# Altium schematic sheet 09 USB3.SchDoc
size 420 x 297 mm
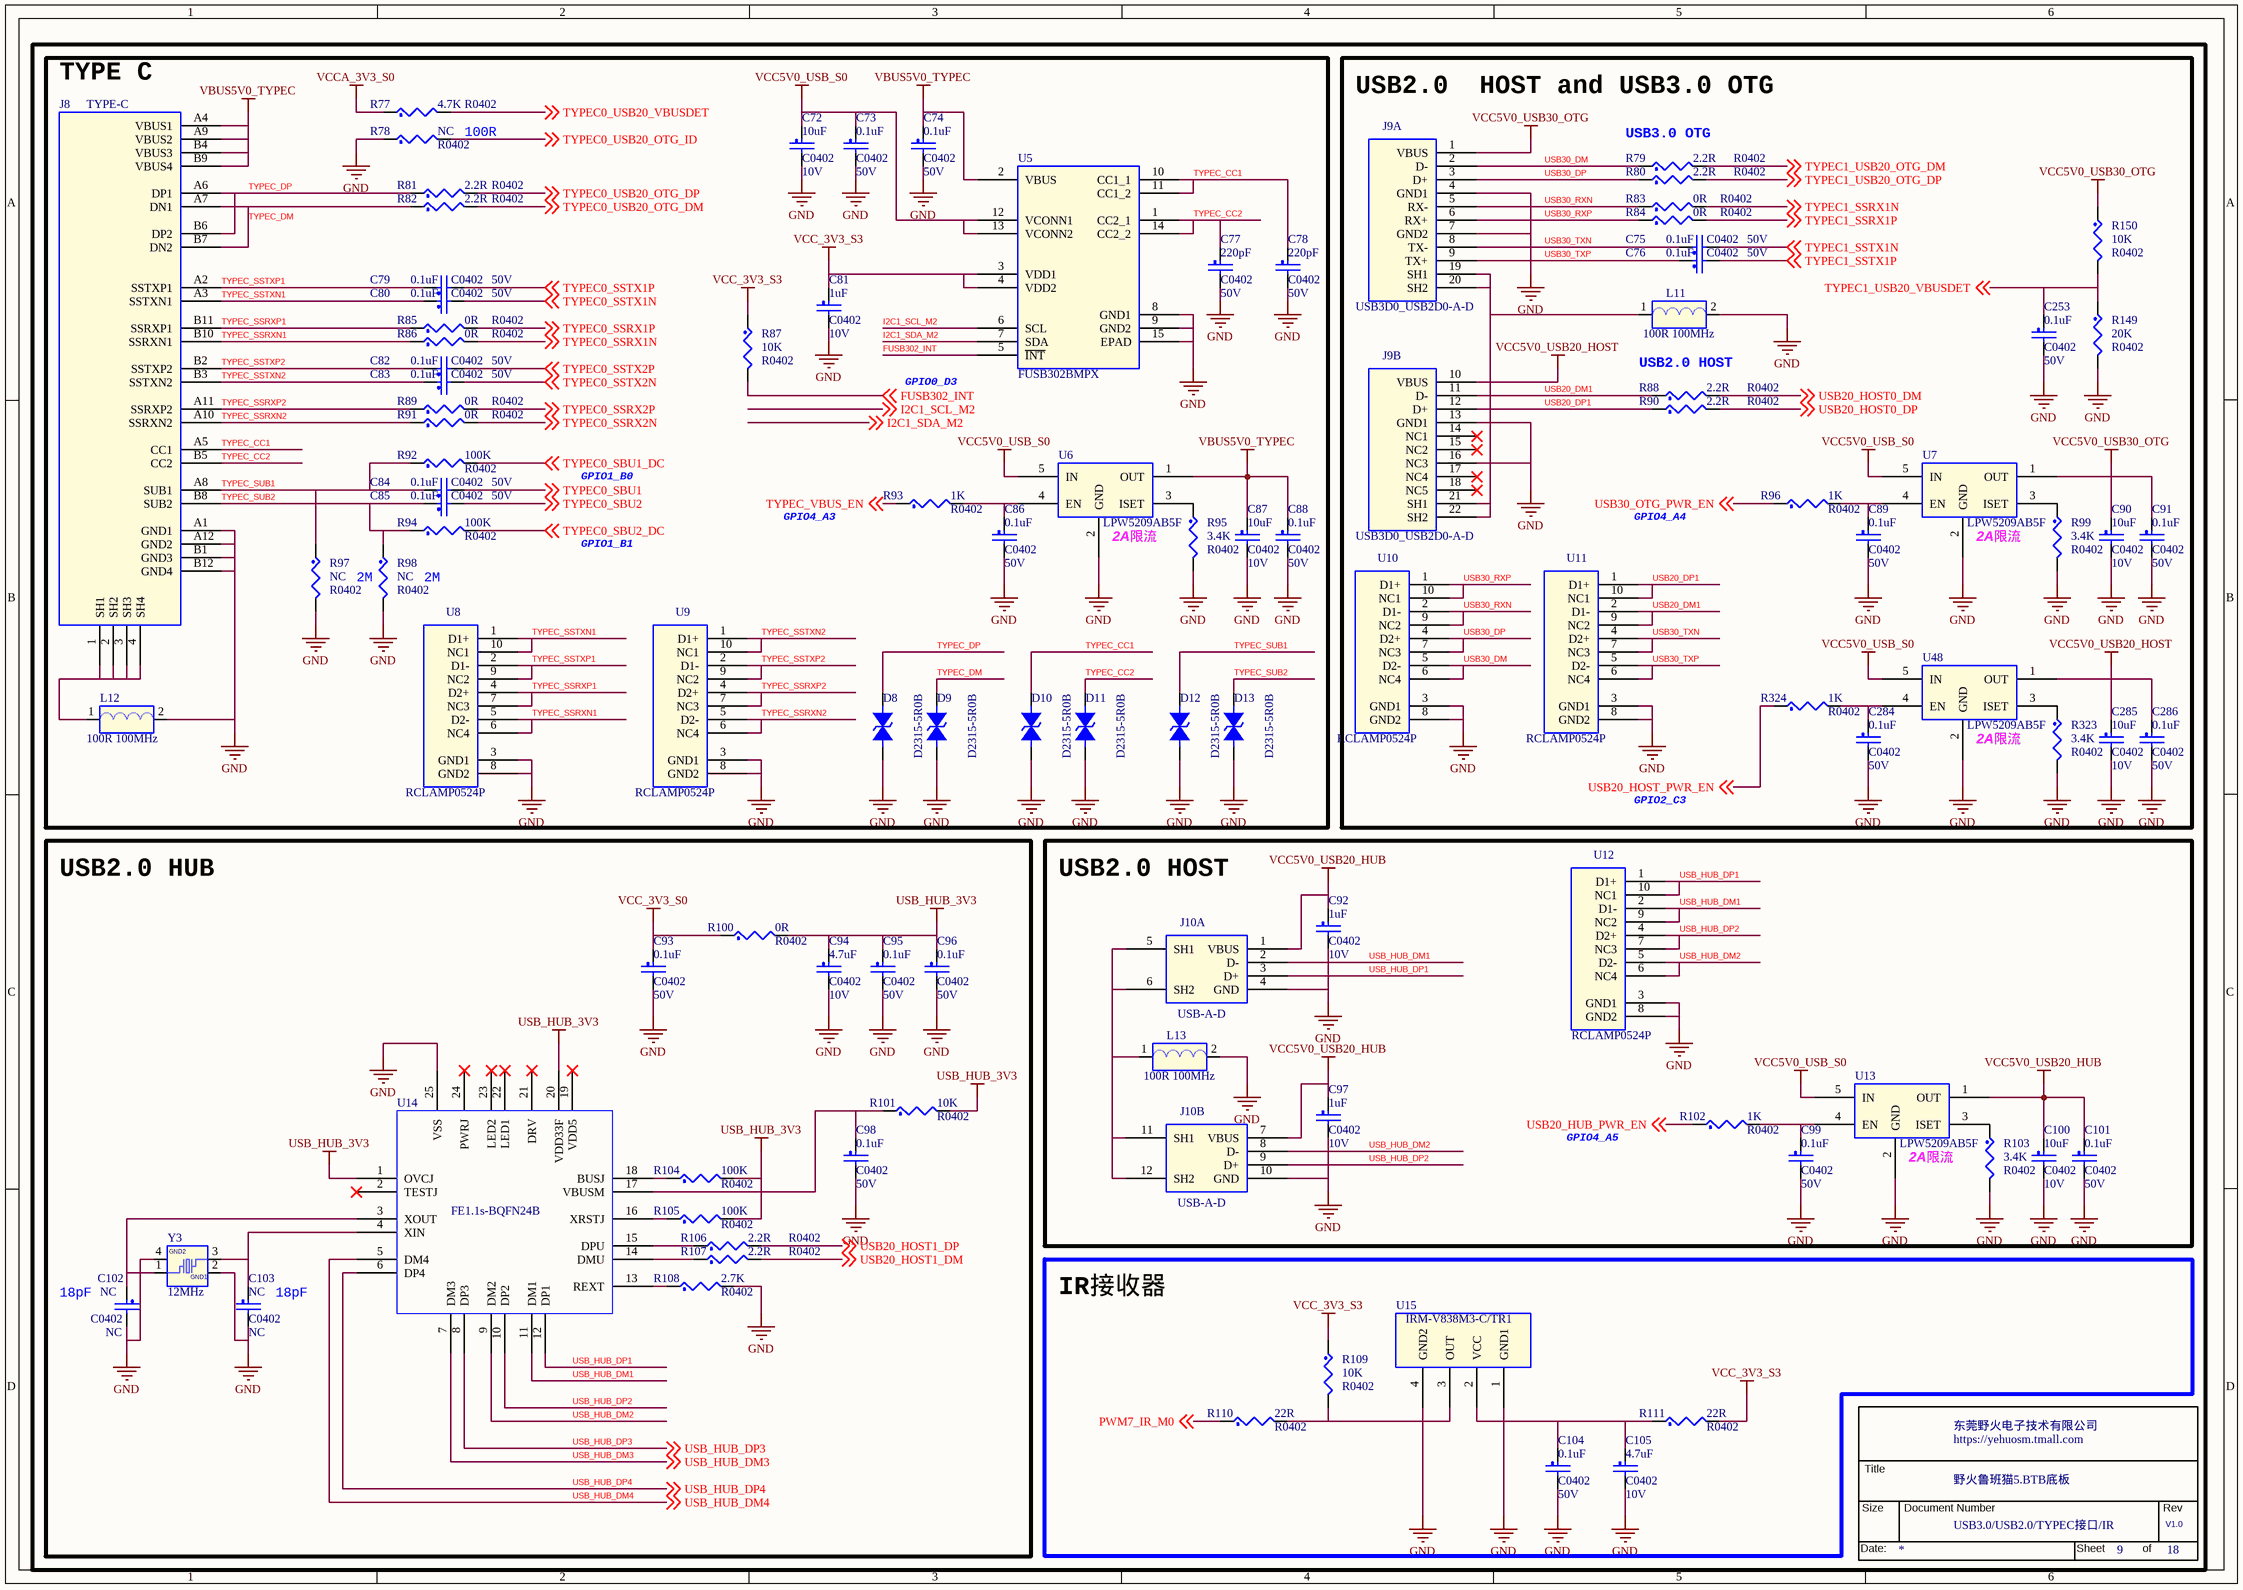
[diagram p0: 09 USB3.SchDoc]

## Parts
*  Doc: USB3.0/USB2.0/TYPEC接口/IR  RevCode: V1.0  Title: 野火鲁班猫5.BTB底板  OrgName: 东莞野火电子技术有限公司  Page Number: 9  Page Count: 18  (hidden comment: TitleBlock_YHSCH)  (graphical)
C72  10uF  Voltage: 10V  [C0402]
C73  0.1uF  Voltage: 50V  [C0402]
C74  0.1uF  Voltage: 50V  [C0402]
C75  0.1uF  Voltage: 50V  [C0402]
C76  0.1uF  Voltage: 50V  [C0402]
C77  220pF  Voltage: 50V  [C0402]
C78  220pF  Voltage: 50V  [C0402]
C79  0.1uF  Voltage: 50V  [C0402]
C80  0.1uF  Voltage: 50V  [C0402]
C81  1uF  Voltage: 10V  [C0402]
C82  0.1uF  Voltage: 50V  [C0402]
C83  0.1uF  Voltage: 50V  [C0402]
C84  0.1uF  Voltage: 50V  [C0402]
C85  0.1uF  Voltage: 50V  [C0402]
C86  0.1uF  Voltage: 50V  [C0402]
C87  10uF  Voltage: 10V  [C0402]
C88  0.1uF  Voltage: 50V  [C0402]
C89  0.1uF  Voltage: 50V  [C0402]
C90  10uF  Voltage: 10V  [C0402]
C91  0.1uF  Voltage: 50V  [C0402]
C92  1uF  Voltage: 10V  [C0402]
C93  0.1uF  Voltage: 50V  [C0402]
C94  4.7uF  Voltage: 10V  [C0402]
C95  0.1uF  Voltage: 50V  [C0402]
C96  0.1uF  Voltage: 50V  [C0402]
C97  1uF  Voltage: 10V  [C0402]
C98  0.1uF  Voltage: 50V  [C0402]
C99  0.1uF  Voltage: 50V  [C0402]
C100  10uF  Voltage: 10V  [C0402]
C101  0.1uF  Voltage: 50V  [C0402]
C102  NC  [C0402]
C103  NC  [C0402]
C104  0.1uF  Voltage: 50V  [C0402]
C105  4.7uF  Voltage: 10V  [C0402]
C253  0.1uF  Voltage: 50V  [C0402]
C284  0.1uF  Voltage: 50V  [C0402]
C285  10uF  Voltage: 10V  [C0402]
C286  0.1uF  Voltage: 50V  [C0402]
D8  D2315-5R0B  [D0603/SMD]
D9  D2315-5R0B  [D0603/SMD]
D10  D2315-5R0B  [D0603/SMD]
D11  D2315-5R0B  [D0603/SMD]
D12  D2315-5R0B  [D0603/SMD]
D13  D2315-5R0B  [D0603/SMD]
J8  TYPE-C  [usb-c-smd_tyc-324g]
J9  USB3D0_USB2D0-A-D  [USB3D0-AF-18P]  (parts A,B of 2)
J10  USB-A-D  [USB-A-D]  (parts A,B of 2)
L11  100R 100MHz  [L0603]
L12  100R 100MHz  [L0603]
L13  100R 100MHz  [L0603]
R77  4.7K  [R0402]
R78  NC  [R0402]
R79  2.2R  [R0402]
R80  2.2R  [R0402]
R81  2.2R  [R0402]
R82  2.2R  [R0402]
R83  0R  [R0402]
R84  0R  [R0402]
R85  0R  [R0402]
R86  0R  [R0402]
R87  10K  [R0402]
R88  2.2R  [R0402]
R89  0R  [R0402]
R90  2.2R  [R0402]
R91  0R  [R0402]
R92  100K  [R0402]
R93  1K  [R0402]
R94  100K  [R0402]
R95  3.4K  [R0402]
R96  1K  [R0402]
R97  NC  [R0402]
R98  NC  [R0402]
R99  3.4K  [R0402]
R100  0R  [R0402]
R101  10K  [R0402]
R102  1K  [R0402]
R103  3.4K  [R0402]
R104  100K  [R0402]
R105  100K  [R0402]
R106  2.2R  [R0402]
R107  2.2R  [R0402]
R108  2.7K  [R0402]
R109  10K  [R0402]
R110  22R  [R0402]
R111  22R  [R0402]
R149  20K  [R0402]
R150  10K  [R0402]
R323  3.4K  [R0402]
R324  1K  [R0402]
U5  FUSB302BMPX  [WQFN14-0R50-2R5X2R5EP1R45X1R45]
U6  LPW5209AB5F  [SOT23-5]
U7  LPW5209AB5F  [SOT23-5]
U8  RCLAMP0524P  [USON_10]
U9  RCLAMP0524P  [USON_10]
U10  RCLAMP0524P  [USON_10]
U11  RCLAMP0524P  [USON_10]
U12  RCLAMP0524P  [USON_10]
U13  LPW5209AB5F  [SOT23-5]
U14  FE1.1s-BQFN24B  [QFN24]
U15  IRM-V838M3-C/TR1  [SMD4-6R80X2R50]
U48  LPW5209AB5F  [SOT23-5]
Y3  12MHz  [3225]

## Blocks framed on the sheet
TYPE C: C72-C74 C77-C88 D8-D13 J8 L12 R77 R78 R81 R82 R85-R87 R89 R91-R95 R97 R98 U5 U6 U8 U9
USB2.0  HOST and USB3.0 OTG: C75 C76 C89-C91 C253 C284-C286 J9 L11 R79 R80 R83 R84 R88 R90 R96 R99 R149 R150 R323 R324 U7 U10 U11 U48
USB2.0 HUB: C93-C96 C98 C102 C103 R100 R101 R104-R108 U14 Y3
USB2.0 HOST: C92 C97 C99-C101 J10 L13 R102 R103 U12 U13
IR接收器: C104 C105 R109-R111 U15

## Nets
GND: C72.2 C73.2 C74.2 C77.2 C78.2 C81.2 C86.2 C87.2 C88.2 C89.2 C90.2 C91.2 C92.2 C93.2 C94.2 C95.2 C96.2 C97.2 C98.2 C99.2 C100.2 C101.2 C102.2 C103.2 C104.2 C105.2 C253.2 C284.2 C285.2 C286.2 D8.1 D9.1 D10.1 D11.1 D12.1 D13.1 J8.A1(GND1) J8.A12(GND2) J8.B1(GND3) J8.B12(GND4) J9.4(GND1) J9.7(GND2) J9.13(GND1) J9.16(NC3) J10.4(GND) J10.10(GND) L11.2 L12.2 L13.2 R78.1 R95.2 R97.2 R98.2 R99.2 R103.2 R108.2 R149.2 R323.2 U5.8(GND1) U5.9(GND2) U5.15(EPAD) U6.2(GND) U7.2(GND) U8.3(GND1) U8.8(GND2) U9.3(GND1) U9.8(GND2) U10.3(GND1) U10.8(GND2) U11.3(GND1) U11.8(GND2) U12.3(GND1) U12.8(GND2) U13.2(GND) U14.25(VSS) U15.1(GND1) U15.4(GND2) U48.2(GND) Y3.2(GND1) Y3.4(GND2)
USB_HUB_3V3: C94.1 C95.1 C96.1 R100.2 R101.2 R104.2 R105.2 U14.1(OVCJ) U14.20(VDD33F)
VBUS5V0_TYPEC: C74.1 C87.1 C88.1 J8.A4(VBUS1) J8.A9(VBUS2) J8.B4(VBUS3) J8.B9(VBUS4) U5.2(VBUS) U6.1(OUT)
VCC5V0_USB20_HOST: C285.1 C286.1 J9.10(VBUS) U48.1(OUT)
VCC5V0_USB20_HUB: C92.1 C97.1 C100.1 C101.1 J10.1(VBUS) J10.7(VBUS) U13.1(OUT)
VCC5V0_USB30_OTG: C90.1 C91.1 J9.1(VBUS) R150.1 U7.1(OUT)
VCC5V0_USB_S0: C72.1 C73.1 U5.12(VCONN1) U5.13(VCONN2) U6.5(IN) U7.5(IN) U13.5(IN) U48.5(IN)
VCC_3V3_S0: C93.1 R100.1
VCC_3V3_S3: C81.1 R87.1 R109.1 R111.2 U5.3(VDD1) U5.4(VDD2)
VCCA_3V3_S0: R77.1
FUSB302_INT: R87.2 U5.5(~{INT}) ; off-sheet FUSB302_INT
I2C1_SCL_M2: U5.6(SCL) ; off-sheet I2C1_SCL_M2
I2C1_SDA_M2: U5.7(SDA) ; off-sheet I2C1_SDA_M2
PWM7_IR_M0: R110.1 ; off-sheet PWM7_IR_M0
TYPEC0_SBU1: C84.2 ; off-sheet TYPEC0_SBU1
TYPEC0_SBU1_DC: R92.2 ; off-sheet TYPEC0_SBU1_DC
TYPEC0_SBU2: C85.2 ; off-sheet TYPEC0_SBU2
TYPEC0_SBU2_DC: R94.2 ; off-sheet TYPEC0_SBU2_DC
TYPEC0_SSRX1N: R86.2 ; off-sheet TYPEC0_SSRX1N
TYPEC0_SSRX1P: R85.2 ; off-sheet TYPEC0_SSRX1P
TYPEC0_SSRX2N: R91.2 ; off-sheet TYPEC0_SSRX2N
TYPEC0_SSRX2P: R89.2 ; off-sheet TYPEC0_SSRX2P
TYPEC0_SSTX1N: C80.2 ; off-sheet TYPEC0_SSTX1N
TYPEC0_SSTX1P: C79.2 ; off-sheet TYPEC0_SSTX1P
TYPEC0_SSTX2N: C83.2 ; off-sheet TYPEC0_SSTX2N
TYPEC0_SSTX2P: C82.2 ; off-sheet TYPEC0_SSTX2P
TYPEC0_USB20_OTG_DM: R82.2 ; off-sheet TYPEC0_USB20_OTG_DM
TYPEC0_USB20_OTG_DP: R81.2 ; off-sheet TYPEC0_USB20_OTG_DP
TYPEC0_USB20_OTG_ID: R78.2 ; off-sheet TYPEC0_USB20_OTG_ID
TYPEC0_USB20_VBUSDET: R77.2 ; off-sheet TYPEC0_USB20_VBUSDET
TYPEC1_SSRX1N: R83.2 ; off-sheet TYPEC1_SSRX1N
TYPEC1_SSRX1P: R84.2 ; off-sheet TYPEC1_SSRX1P
TYPEC1_SSTX1N: C75.2 ; off-sheet TYPEC1_SSTX1N
TYPEC1_SSTX1P: C76.2 ; off-sheet TYPEC1_SSTX1P
TYPEC1_USB20_OTG_DM: R79.2 ; off-sheet TYPEC1_USB20_OTG_DM
TYPEC1_USB20_OTG_DP: R80.2 ; off-sheet TYPEC1_USB20_OTG_DP
TYPEC1_USB20_VBUSDET: C253.1 R149.1 R150.2 ; off-sheet TYPEC1_USB20_VBUSDET
TYPEC_CC1: C78.1 D10.2 J8.A5(CC1) U5.10(CC1_1) U5.11(CC1_2)
TYPEC_CC2: C77.1 D11.2 J8.B5(CC2) U5.1(CC2_1) U5.14(CC2_2)
TYPEC_DM: D9.2 J8.A7(DN1) J8.B7(DN2) R82.1
TYPEC_DP: D8.2 J8.A6(DP1) J8.B6(DP2) R81.1
TYPEC_SSRXN1: J8.B10(SSRXN1) R86.1 U8.5(D2-) U8.6(NC4)
TYPEC_SSRXN2: J8.A10(SSRXN2) R91.1 U9.5(D2-) U9.6(NC4)
TYPEC_SSRXP1: J8.B11(SSRXP1) R85.1 U8.4(D2+) U8.7(NC3)
TYPEC_SSRXP2: J8.A11(SSRXP2) R89.1 U9.4(D2+) U9.7(NC3)
TYPEC_SSTXN1: C80.1 J8.A3(SSTXN1) U8.1(D1+) U8.10(NC1)
TYPEC_SSTXN2: C83.1 J8.B3(SSTXN2) U9.1(D1+) U9.10(NC1)
TYPEC_SSTXP1: C79.1 J8.A2(SSTXP1) U8.2(D1-) U8.9(NC2)
TYPEC_SSTXP2: C82.1 J8.B2(SSTXP2) U9.2(D1-) U9.9(NC2)
TYPEC_SUB1: C84.1 D12.2 J8.A8(SUB1) R92.1 R97.1
TYPEC_SUB2: C85.1 D13.2 J8.B8(SUB2) R94.1 R98.1
TYPEC_VBUS_EN: R93.1 ; off-sheet TYPEC_VBUS_EN
USB20_DM1: J9.11(D-) R88.1 U11.2(D1-) U11.9(NC2)
USB20_DP1: J9.12(D+) R90.1 U11.1(D1+) U11.10(NC1)
USB20_HOST0_DM: R88.2 ; off-sheet USB20_HOST0_DM
USB20_HOST0_DP: R90.2 ; off-sheet USB20_HOST0_DP
USB20_HOST1_DM: R107.2 ; off-sheet USB20_HOST1_DM
USB20_HOST1_DP: R106.2 ; off-sheet USB20_HOST1_DP
USB20_HOST_PWR_EN: R324.1 ; off-sheet USB20_HOST_PWR_EN
USB20_HUB_PWR_EN: R102.1 ; off-sheet USB20_HUB_PWR_EN
USB30_DM: J9.2(D-) R79.1 U10.5(D2-) U10.6(NC4)
USB30_DP: J9.3(D+) R80.1 U10.4(D2+) U10.7(NC3)
USB30_OTG_PWR_EN: R96.1 ; off-sheet USB30_OTG_PWR_EN
USB30_RXN: J9.5(RX-) R83.1 U10.2(D1-) U10.9(NC2)
USB30_RXP: J9.6(RX+) R84.1 U10.1(D1+) U10.10(NC1)
USB30_TXN: C75.1 J9.8(TX-) U11.4(D2+) U11.7(NC3)
USB30_TXP: C76.1 J9.9(TX+) U11.5(D2-) U11.6(NC4)
USB_HUB_DM1: J10.2(D-) U12.2(D1-) U12.9(NC2) U14.11(DM1)
USB_HUB_DM2: J10.8(D-) U12.5(D2-) U12.6(NC4) U14.9(DM2)
USB_HUB_DM3: U14.7(DM3) ; off-sheet USB_HUB_DM3
USB_HUB_DM4: U14.5(DM4) ; off-sheet USB_HUB_DM4
USB_HUB_DP1: J10.3(D+) U12.1(D1+) U12.10(NC1) U14.12(DP1)
USB_HUB_DP2: J10.9(D+) U12.4(D2+) U12.7(NC3) U14.10(DP2)
USB_HUB_DP3: U14.8(DP3) ; off-sheet USB_HUB_DP3
USB_HUB_DP4: U14.6(DP4) ; off-sheet USB_HUB_DP4
NetC86_1: C86.1 R93.2 U6.4(EN)
NetC89_1: C89.1 R96.2 U7.4(EN)
NetC98_1: C98.1 R101.1 U14.17(VBUSM)
NetC99_1: C99.1 R102.2 U13.4(EN)
NetC102_1: C102.1 U14.3(XOUT) Y3.1
NetC103_1: C103.1 U14.4(XIN) Y3.3
NetC104_1: C104.1 C105.1 R111.1 U15.2(VCC)
NetC284_1: C284.1 R324.2 U48.4(EN)
NetJ8_1: J8.1(SH1) J8.2(SH2) J8.3(SH3) J8.4(SH4) L12.1
NetJ9_19: J9.19(SH1) J9.20(SH2) J9.21(SH1) J9.22(SH2) L11.1
NetJ10_5: J10.5(SH1) J10.6(SH2) J10.11(SH1) J10.12(SH2) L13.1
NetR95_1: R95.1 U6.3(ISET)
NetR99_1: R99.1 U7.3(ISET)
NetR103_1: R103.1 U13.3(ISET)
NetR104_1: R104.1 U14.18(BUSJ)
NetR105_1: R105.1 U14.16(XRSTJ)
NetR106_1: R106.1 U14.15(DPU)
NetR107_1: R107.1 U14.14(DMU)
NetR108_1: R108.1 U14.13(REXT)
NetR109_2: R109.2 R110.2 U15.3(OUT)
NetR323_1: R323.1 U48.3(ISET)

Not connected (* = marked no-connect by the designer): J9 14(NC1)* 15(NC2)* 17(NC4)* 18(NC5)*; U14 2(TESTJ)* 19(VDD5)* 21(DRV)* 22(LED1)* 23(LED2)* 24(PWRJ)*

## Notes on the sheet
- 100R
- USB3.0 OTG
- GPIO0_D3
- USB2.0 HOST
- GPIO1_B0
- GPIO4_A3
- GPIO4_A4
- (near R98) 2M
- 2M
- GPIO1_B1
- (near U6) 2A限流
- (near U7) 2A限流
- GPIO2_C3
- (near U48) 2A限流
- GPIO4_A5
- (near U13) 2A限流
- (near C102) 18pF
- (near C103) 18pF

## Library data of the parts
* = TitleBlock_YHSCH: Cage Code: 1
C72 C87 C90 C100 C285 = CAP_NP: CLASS: DISCRETE; 规格: 贴片电容10uF 20% 10V X5R 0402; 规格编号: CL05A106MP8NUB8; 条码: EBF29060247; 品牌: 三星; 类别: 贴片电容0402; 规格书: 三星电容.pdf; 价格: 0.518415; 生命周期: 量产
C73 C75 C79 C80 C82-C86 C88 C89 C91 C93 C95 C96 C98 C99 C101 C104 C253 C284 C286 = CAP_NP: CLASS: DISCRETE; 生命周期: 量产; 价格: 0.029826; 规格书: 风华电容.pdf; 类别: 贴片电容0402; 品牌: 风华; 条码: EBF29060118; 规格编号: 0402X104K500NT; 规格: 贴片电容0.1uF 10% 50V X5R 0402
C74 C76 = CAP_NP: CLASS: DISCRETE; 规格: 贴片电容0.1uF 10% 50V X5R 0402; 规格编号: 0402X104K500NT; 条码: EBF29060118; 品牌: 风华; 类别: 贴片电容0402; 规格书: 风华电容.pdf; 价格: 0.029826; 生命周期: 量产
C77 = CAP_NP: CLASS: DISCRETE; 价格: 0.00358; 规格书: 风华电容.pdf; 类别: 贴片电容0402; 品牌: 风华; 条码: EBFCIS221112143723; 规格编号: 0402B221K500NT; 规格: 贴片电容220pF 10% 50V X7R 0402
C78 = CAP_NP: CLASS: DISCRETE; 规格: 贴片电容220pF 10% 50V X7R 0402; 规格编号: 0402B221K500NT; 条码: EBFCIS221112143723; 品牌: 风华; 类别: 贴片电容0402; 规格书: 风华电容.pdf; 价格: 0.00358
C81 = CAP_NP: CLASS: DISCRETE; 规格: 贴片电容1uF 10% 10V X5R 0402; 规格编号: 0402X105K100NT; 条码: EBF29060121; 品牌: 风华; 类别: 贴片电容0402; 规格书: 风华电容.pdf; 价格: 0.01191; 生命周期: 量产
C92 C97 = CAP_NP: CLASS: DISCRETE; 生命周期: 量产; 价格: 0.01191; 规格书: 风华电容.pdf; 类别: 贴片电容0402; 品牌: 风华; 条码: EBF29060121; 规格编号: 0402X105K100NT; 规格: 贴片电容1uF 10% 10V X5R 0402
C94 = CAP_NP: CLASS: DISCRETE; 生命周期: 量产; 价格: 0.059058; 规格书: 国巨-贴片电容.pdf; 类别: 贴片电容0402; 品牌: 国巨; 条码: EBF29060248; 规格编号: CC0402KRX5R6BB475; 规格: 贴片电容4.7uF 10% 10V X5R 0402
C102 = CAP_NP: CLASS: DISCRETE; 类别: 贴片电容0402; 条码: EBF29060149; 规格: 贴片电容NC 预留
C103 = CAP_NP: CLASS: DISCRETE; 规格: 贴片电容NC 预留; 条码: EBF29060149; 类别: 贴片电容0402
C105 = CAP_NP: CLASS: DISCRETE; 规格: 贴片电容4.7uF 10% 10V X5R 0402; 规格编号: CC0402KRX5R6BB475; 条码: EBF29060248; 品牌: 国巨; 类别: 贴片电容0402; 规格书: 国巨-贴片电容.pdf; 价格: 0.059058; 生命周期: 量产
D8-D13 = DIODE BI-DIR TRIG: PCB Footprint: esd0402; 备注: 通用; 生命周期: 量产; 规格书: 千虹_D2315-5R0B.pdf; 类别: 贴片ESD; 品牌: 千虹; 条码: EBFCIS240517170922; 规格: 防静电保护ESD二极管 反向工作电压5V 击穿电压7V 钳位电压10.5V 结电容Cj 0.3pF
J8 = TYPE-C-24P: 规格书: 讯普_TYC-324G.pdf; 类别: USB接口; 品牌: 讯普; 条码: EBFCIS220922094113; 规格编号: TYC-324G; 规格: Type-C母座 24P USB-3.1 插座 4固定脚 双向
J9 = USB3D0_USB2D0-A-D: 品牌: 富士康; 生命周期: 量产; 规格书: UEA1112C-UHS6-4F.pdf; 类别: USB接口; 条码: EBF29040092; 规格编号: UEA1112C-UHS6-4F; 规格: USB3.0_USB2.0母座
J10 = USB-A-D: 规格: 双层USB接口 A型接口 90度双排弯插脚 AF母座 焊接式; 规格编号: 907-111A1012D10200; 条码: EBF29020027; 品牌: 精拓金; 类别: USB接口; 规格书: 精拓金-双层USB.pdf; 价格: 0.22; 生命周期: 量产
L11 L13 = BEAD: CLASS: DISCRETE; 生命周期: 量产; 价格: 0.021567; 规格书: 顺络-磁珠.pdf; 类别: 贴片磁珠0603; 品牌: 顺络; 条码: EBF29050038; 规格编号: UPZ1608E101-3R0TF; 规格: 磁珠100Ω @100MHz 额定电流3A 直流电阻30mΩ
L12 = BEAD: CLASS: DISCRETE; 规格: 磁珠100Ω @100MHz 额定电流3A 直流电阻30mΩ; 规格编号: UPZ1608E101-3R0TF; 条码: EBF29050038; 品牌: 顺络; 类别: 贴片磁珠0603; 规格书: 顺络-磁珠.pdf; 价格: 0.021567; 生命周期: 量产
R77 = RES: CLASS: DISCRETE; 规格: 贴片电阻4.7K 1% 1/16W 0402; 规格编号: RI0402L4701FT; 条码: EBF29070047; 品牌: 合科泰; 类别: 贴片电阻0402; 规格书: 合科泰-RI系列电阻.pdf; 生命周期: 量产
R78 R97 = RES: CLASS: DISCRETE; 类别: 贴片电阻0402; 条码: EBF29070087; 规格: 贴片电阻NC 预留
R79-R82 R88 = RES: CLASS: DISCRETE; 生命周期: 量产; 价格: 0.003072; 规格书: 厚声-无铅厚膜电阻.pdf; 类别: 贴片电阻0402; 品牌: 厚声; 条码: EBF29070280; 规格编号: 0402WGF220KTCE; 规格: 贴片电阻2.2R 1% 1/16W 0402
R83-R86 R89 R91 = RES: CLASS: DISCRETE; 规格: 贴片电阻0R 1% 1/16W 0402; 规格编号: RI0402L000FT; 条码: EBF29070049; 品牌: 合科泰; 类别: 贴片电阻0402; 规格书: 合科泰-RI系列电阻.pdf; 生命周期: 量产
R87 R109 = RES: CLASS: DISCRETE; 生命周期: 量产; 价格: 0.002773; 规格书: 厚声-无铅厚膜电阻.pdf; 类别: 贴片电阻0402; 品牌: 厚声; 条码: EBF29070046; 规格编号: 0402WGF1002TCE; 规格: 贴片电阻10K 1% 1/16W 0402
R90 R106 R107 = RES: CLASS: DISCRETE; 规格: 贴片电阻2.2R 1% 1/16W 0402; 规格编号: 0402WGF220KTCE; 条码: EBF29070280; 品牌: 厚声; 类别: 贴片电阻0402; 规格书: 厚声-无铅厚膜电阻.pdf; 价格: 0.003072; 生命周期: 量产
R92 R94 R104 R105 = RES: CLASS: DISCRETE; 规格: 贴片电阻100K 1% 1/16W 0402; 规格编号: RI0402L1003FT; 条码: EBF29070054; 品牌: 合科泰; 类别: 贴片电阻0402; 规格书: 合科泰-RI系列电阻.pdf; 生命周期: 量产
R93 R102 = RES: CLASS: DISCRETE; 规格: 贴片电阻1K 1% 1/16W 0402; 规格编号: RI0402L1001FT; 条码: EBF29070050; 品牌: 合科泰; 类别: 贴片电阻0402; 规格书: 合科泰-RI系列电阻.pdf; 生命周期: 量产
R95 R99 R103 R323 = RES: CLASS: DISCRETE; 生命周期: 量产; 规格书: 合科泰-RI系列电阻.pdf; 类别: 贴片电阻0402; 品牌: 合科泰; 条码: EBF29070186; 规格编号: RI0402L3401FT; 规格: 贴片电阻3.4K 1% 1/16W 0402
R96 R324 = RES: CLASS: DISCRETE; 生命周期: 量产; 规格书: 合科泰-RI系列电阻.pdf; 类别: 贴片电阻0402; 品牌: 合科泰; 条码: EBF29070050; 规格编号: RI0402L1001FT; 规格: 贴片电阻1K 1% 1/16W 0402
R98 = RES: CLASS: DISCRETE; 规格: 贴片电阻NC 预留; 条码: EBF29070087; 类别: 贴片电阻0402
R100 = RES: CLASS: DISCRETE; 生命周期: 量产; 规格书: 合科泰-RI系列电阻.pdf; 类别: 贴片电阻0402; 品牌: 合科泰; 条码: EBF29070049; 规格编号: RI0402L000FT; 规格: 贴片电阻0R 1% 1/16W 0402
R101 R150 = RES: CLASS: DISCRETE; 规格: 贴片电阻10K 1% 1/16W 0402; 规格编号: 0402WGF1002TCE; 条码: EBF29070046; 品牌: 厚声; 类别: 贴片电阻0402; 规格书: 厚声-无铅厚膜电阻.pdf; 价格: 0.002773; 生命周期: 量产
R108 = RES: CLASS: DISCRETE; 规格: 贴片电阻2.7K 1% 1/16W 0402; 规格编号: RMC04022.7K1%N; 条码: EBF29070202; 品牌: 幸亚; 类别: 贴片电阻0402; 规格书: 幸亚电阻.pdf; 价格: 0.016497; 生命周期: 量产
R110 R111 = RES: CLASS: DISCRETE; 规格: 贴片电阻22R 1% 1/16W 0402; 规格编号: RI0402L22R0FT; 条码: EBF29070181; 品牌: 合科泰; 类别: 贴片电阻0402; 规格书: 合科泰-RI系列电阻.pdf; 生命周期: 量产
R149 = RES: CLASS: DISCRETE; 生命周期: 量产; 价格: 0.002473; 规格书: 厚声-无铅厚膜电阻.pdf; 类别: 贴片电阻0402; 品牌: 厚声; 条码: EBF29070223; 规格编号: 0402WGF2002TCE; 规格: 贴片电阻20K 1% 1/16W 0402
U5 = FUSB302BMPX: 生命周期: 量产; 价格: 3.8016; 规格书: 安森美_FUSB302BMPX.pdf; 类别: USB芯片; 品牌: 安森美; 条码: EBFCIS221116112239; 规格: 可编程USB Type-C控制器 支持USB Type-C检测 带PD 可实现高达 100 W 的电源和角色互换
U6 U7 U13 U48 = LPW5209AB5F: 生命周期: 量产; 价格: 0.468063; 规格书: 微源半导体_LPW5209AB5F.pdf; 类别: 功率开关; 品牌: 微源半导体; 条码: EBF29280015; 规格: 集成电源开关 导通电阻：80mΩ 最大可设置保护电流：2.1A 输入电压：2.5V~6V 静态电流：30uA 其他功能：软启动、短路保护、热保护
U8 U9 U12 = RCLAMP0524P: 规格: TVS二极管 箝位电压17V 击穿电压8V 反向关断电压5V; 条码: EBF29140046; 品牌: 台舟; 类别: 贴片四路ESD; 规格书: 台舟-RCLAMP0524P.pdf; 价格: 0.185957; 生命周期: 量产
U10 U11 = RCLAMP0524P: 生命周期: 量产; 价格: 0.185957; 规格书: 台舟-RCLAMP0524P.pdf; 类别: 贴片四路ESD; 品牌: 台舟; 条码: EBF29140046; 规格: TVS二极管 箝位电压17V 击穿电压8V 反向关断电压5V
U14 = FE1.1s-BQFN24B: 生命周期: 量产; 规格书: FE1.1s-BQFN24B.pdf; 类别: USB芯片; 品牌: 汤铭科技; 条码: EBF29150035; 规格: USB HUB芯片 工作电压3.3V 5V 协议类别USB2.0 支持高速(480Mbps) 全速(12Mbps)和低速(1.5Mbps)模式
U15 = IRM-V838M3-C/TR1: 规格: 侧贴红外遥控接收头 工作电压2.7V~5.5V 兼容TTL与CMOS; 条码: EBF29230005; 品牌: 亿光; 类别: 红外接收头; 规格书: IRM-V838M3-C_TR1.pdf; 生命周期: 量产
Y3 = CRYSTAL_4P: CLASS: IC; 规格: 无源晶振12MHZ 80Ω 20pF 3225; 规格编号: X322512MSB4SI; 条码: EBF29100013; 品牌: 扬兴科技; 类别: 贴片晶振 3225; 规格书: 扬兴科技-贴片晶振.pdf; 价格: 0.327763; 生命周期: 量产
